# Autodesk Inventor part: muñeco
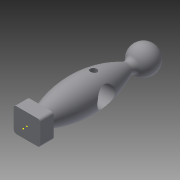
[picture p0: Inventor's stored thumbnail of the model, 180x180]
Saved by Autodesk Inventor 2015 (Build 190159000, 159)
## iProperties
Created: 2016-05
Part Number: muñeco
Material: Genérico
Document SubType Name: Modeling
Designer: ALEX
Density: 1 g/cm^3
Appearance: Valor por defecto
Author: ALEX
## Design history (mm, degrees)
sketch "Boceto1"
  geometry: L1 (0, 0)-(0, 100.375); L2 (0, 88.193)-(0, 73.709); L3 (-6, 12.866)-(0, 12.866); A1 r 10 centre (0, 90.375) between (0, 100.375) and (-5.979, 82.359); A2 r 78 centre (65.821, 43.292) between (-4.606, 76.818) and (-6, 12.866); A3 r 4.5 centre (-8.669, 78.752) between (-4.606, 76.818) and (-5.979, 82.359)
  constraints: 6 end point, 6 point on circle, 3 centre point, 3 point on line, 2 tangent, 1 horizontal, 1 vertical
  dimensions: "d1" = 78 radius of A2; "d2" = 10 radius of A1; "d3" = 6 distance of L3.start L3.end; "d4" = 9 diameter of A3
revolve "Revolución1" sketch "Boceto1" stored, may be unused: angle "d5" = 90 deg
sketch "Boceto2"
  geometry: L1 (10, 9.091)-(-10, 9.091); L2 (-10, 9.091)-(-10, -9.091); L3 (-10, -9.091)-(10, -9.091); L4 (10, -9.091)-(10, 9.091); L5 (10, 9.091)-(-10, -9.091); L6 (-10, 9.091)-(10, -9.091); 1 further point
  constraints: 12 end point, 2 midpoint, 2 parallel, 1 horizontal, 1 perpendicular
  dimensions: "d6" = 20 distance of L3.end L2.end
extrude "Extrusión1" join sketch "Boceto2" distance "d7" = 10; taper "d8" = 0 deg
fillet "Empalme1" dims "d9" = 2
fillet "Empalme2" dims "d10" = 2
fillet "Empalme3" dims "d11" = 2
fillet "Empalme4" dims "d12" = 2
sketch "Boceto3"
  geometry: 1 further point
fillet "Empalme5" dims "d13" = 2
sketch "Boceto4"
  geometry: 1 further point
node "Plano de trabajo1"
sketch "Boceto5"
  geometry: C1 r 7.5 at (-39.281, 0); 1 further point
  constraints: 1 centre point
  dimensions: "d14" = 15 diameter of C1
extrude "Extrusión2" cut sketch "Boceto5" stored distance "d15" = 50; taper "d16" = 0 deg
node "Plano de trabajo2"
sketch "Boceto6"
  geometry: C1 r 2.5 at (0, 52.814); 1 further point
  constraints: 1 centre point
  dimensions: "d17" = 5 diameter of C1
extrude "Extrusión3" cut sketch "Boceto6" stored distance "d18" = 50; taper "d19" = 0 deg
node "Sólido1"
